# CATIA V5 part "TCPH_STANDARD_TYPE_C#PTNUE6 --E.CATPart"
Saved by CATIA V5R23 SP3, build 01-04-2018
Part number: TCPH_STANDARD_TYPE_C#PTNUDR
Revision: --E
Nomenclature: _
Description: TCPH_STANDARD_TYPE_C
Property "AT": "PD"
Property "REP": "CM"
Property "External Part ID": "_"
Property "Description Modification": "DR-34 and DR-35"
Property "PREF": "Y"
Property "LONG": "_"
Property "PBS 1": "24"
Property "PBS 2": "CR"
Property "PBS 3": "LC"
Property "DEPT": "_"
Property "DIVN": "_"
Property "GROUP": "_"
Property "UNIT": "_"
Property "PARTY": "_"
Property "RO": "BHARDWA"
Property "RE": "VITUPIG"
Property "PRO": "---"
Property "Change Type": "Minor"
Property "Maturity Level": "CD"
Property "Export Number": "_"
Property "Description Documents": "_"
Property "BOM": "_"
Property "ID": "PTNUDR"
Property "User In Enovia": "VAUQUEJ"
Property "Object Type": "_"
Property "CADENAS_ID": "_"
Property "Life Cycle Status": "Approved"
Material "Stainless Steel": density 8030 kg/m3, Young's modulus 2e+11 Pa, Poisson ratio 0.266, thermal expansion 1.17e-05 1/K
Bounding box of the stored display mesh (mm): x 13380 to 16870, y -1350 to 1350, z -6313 to -2983
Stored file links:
  C:\Users\pandeym\Desktop\__TCPH\TCPH_STANDARD_TYPE_C#PTNUE6 --E.CATPart
  C:\Users\pandeym\Desktop\__TCPH\TCPH_STANDARD_TYPE_B#MQ4XK3 --F.CATPart
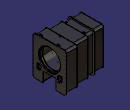
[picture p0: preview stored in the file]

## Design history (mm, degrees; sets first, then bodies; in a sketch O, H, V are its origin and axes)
Set1
  Sketch1 "LIFTING_PADS_HOLES", origin (0, 0, -3193), H (1, 0, 0), V (0, 1, 0), geometry linked from another document
  Sketch2 "LIFTING_PADS", origin (0, 0, -3193), H (1, 0, 0), V (0, 1, 0), geometry linked from another document
Body1 (main body)
Body2 "SHELL"
  Solid1: linked copy from another document
  Symmetry1: ToTransfor Solid1, Reference zx-plane
Body3 "INTERFACE_PLATE"
  Solid2: linked copy from another document
  Symmetry2: ToTransfor Solid2, Reference zx-plane
Body4 "VERTICAL_PLATES"
  Solid3: linked copy from another document
  Symmetry3: ToTransfor Solid3, Reference zx-plane
Body5 "FLANGE"
  Solid4: linked copy from another document
  Symmetry4: ToTransfor Solid4, Reference zx-plane
Body6 "INNER_CYLINDER"
  Solid5: linked copy from another document
Body7 "POCKET"
  Solid6: linked copy from another document
Body8 "TUBE_B1_TO_B5"
  Solid7: linked copy from another document
  Symmetry5: ToTransfor Solid7, Reference zx-plane
  Sketch3 "LIFTING_PADS", origin (0, 0, -3193), H (1, 0, 0), V (0, 1, 0), geometry linked from another document
Body9 "RH_POCKET"
  Solid8: linked copy from another document
Body10 "VACUUM_PIPE"
  Solid9: linked copy from another document
  Symmetry6: ToTransfor Solid9, Reference zx-plane
Body11 "LIFTING_PADS"
  Pad1: profile Sketch3, direction (0, 0, 1), length 60
  Sketch4 on end face of Pad1, origin (15830, 0, -3133), H (1, 0, 0), V (0, 1, 0)
    point P1 (100, 0)
    reference projected point E1 (100, 0) from vertex of Sketch1
    coincidence: E1 P1
  Hole1: placed by Sketch4, at (15930, 0, -3133) direction (0, 0, -1), diameter 31.67, through (limit type 3), threaded "M36", thread diameter 36, thread depth 60, pitch 4
  UserPattern1: of Hole1, copies 3, at the points of Sketch1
